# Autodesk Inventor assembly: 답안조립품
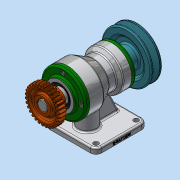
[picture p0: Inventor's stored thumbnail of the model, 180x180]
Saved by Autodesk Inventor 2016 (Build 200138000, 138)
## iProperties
Created: 2019-01
Part Number: 답안조립품
Material: 일반
Document SubType Name: Assembly
Designer: Administrator
Author: Administrator
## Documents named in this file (15)
- C:\Users\Administrator\Desktop\490107V1023\답안조립품.iam
- C:\Users\Administrator\Desktop\490107V1023\본체.ipt
- C:\Users\Administrator\Desktop\490107V1023\축.ipt
- C:\Users\Administrator\Desktop\490107V1023\베어링 6203.ipt
- C:\Users\Administrator\Desktop\490107V1023\뒤커버.ipt
- C:\Users\Administrator\Desktop\490107V1023\볼트 M4.ipt
- C:\Users\Administrator\Desktop\490107V1023\오일 실 17 30 8.ipt
- C:\Users\Administrator\Desktop\490107V1023\키 5 x 5 x 20.ipt
- C:\Users\Administrator\Desktop\490107V1023\V-벨트풀리.ipt
- C:\Users\Administrator\Desktop\490107V1023\멈춤나사 M3.ipt
- C:\Users\Administrator\Desktop\490107V1023\베어링 6205.ipt
- C:\Users\Administrator\Desktop\490107V1023\앞커버.ipt
- C:\Users\Administrator\Desktop\490107V1023\오일 실 25 38 8.ipt
- C:\Users\Administrator\Desktop\490107V1023\키 6 x 6 x 18.ipt
- C:\Users\Administrator\Desktop\490107V1023\스퍼기어.ipt
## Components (1 placed, 1 different names)
1. V-벨트풀리:1
